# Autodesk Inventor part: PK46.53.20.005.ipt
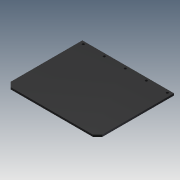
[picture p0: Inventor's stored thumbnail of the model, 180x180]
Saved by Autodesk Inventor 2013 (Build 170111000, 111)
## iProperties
Created: 2005-03
Part Number: PK46.53.20.005.ipt
Material: Silicone
Document SubType Name: Modeling
Designer: HKostja
Manufacturer: Standard
Standards Organization: Custom
Density: 1.25 g/cm^3
Mass: 2385.12 g
Surface Area: 4008.11 cm^2
Volume: 1908.1 cm^3
Author: HKostja
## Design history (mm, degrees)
sketch "Эскиз1" dims "d14" = 10
  geometry: L1 (0, 0)-(-480, 0); L2 (-480, 0)-(-480, -375); L3 (-455, -400)-(-25, -400); L4 (0, -375)-(0, 0); L5 (-480, -375)-(-455, -400); L6 (-25, -400)-(0, -375); C1 r 6 at (-460, -15); C2 r 6 at (-350, -15); C3 r 6 at (-240, -15); C4 r 6 at (-130, -15); C5 r 6 at (-20, -15); 2 further points
  constraints: 12 end point, 5 centre point, 4 point on line, 2 horizontal, 2 parallel, 1 perpendicular, 9 other
  dimensions: "d0" = 400 distance between parallel lines of L1 L3; "d1" = 480 distance between parallel lines of L2 L4; "d2" = 25 distance of L2.end point (-480, -400); "d3" = 25 distance of L3.start point (-480, -400) (= d2); "d4" = 25 distance of L3.end point (0, -400) (= d2); "d5" = 25 distance of L4.start point (0, -400) (= d4); "d6" = 12 diameter of C1; "d7" = 15 distance from line of L1 C1.centre; "d8" = 20 distance from line of L2 C1.centre; "d11" = 110 distance of C1.centre C2.centre
extrude "Выдавливание1" new body sketch "Эскиз1" distance "d16" = 10; taper "d17" = 0 deg
body "Solid1"
